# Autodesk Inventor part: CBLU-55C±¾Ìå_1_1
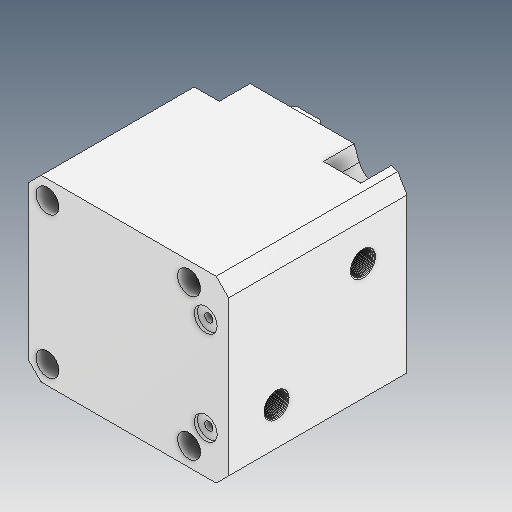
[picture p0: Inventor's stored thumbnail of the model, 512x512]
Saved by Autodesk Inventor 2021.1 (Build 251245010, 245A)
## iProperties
Created: 2021-05
Part Number: CBLU-55C±¾Ìå_1_1
Material: Ogólny
Document SubType Name: Modeling
Designer: user
Density: 1 g/cm^3
Appearance: Domyślna
Author: user
Revision Number: ÈÎºÎ
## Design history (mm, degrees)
feature "ÊäÈë2"
feature "ÊäÈë3"
feature "ÊäÈë4"
feature "ÇÐ³ý-À­Éì1" [ÊäÈë]
node "Bryła1"
node "Bryła2"
node "Bryła3"
node "Bryła4"
